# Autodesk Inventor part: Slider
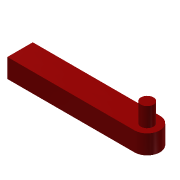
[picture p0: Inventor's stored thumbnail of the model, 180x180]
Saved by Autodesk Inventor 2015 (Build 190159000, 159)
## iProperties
Created: 2019-10
Part Number: Slider
Material: 一般
Document SubType Name: Modeling
Designer: Kuan_Lun Hsu
Density: 1 g/cm^3
Appearance: 紅
Mass: 268.274 g
Surface Area: 342.265 cm^2
Volume: 268.274 cm^3
Author: Kuan_Lun Hsu
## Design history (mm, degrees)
sketch "草圖1" dims "d4" = 60
  geometry: L1 (0, 220)-(200, 220); L2 (200, 220)-(200, 180); L3 (200, 180)-(0, 180); L4 (0, 180)-(0, 220); L5 (-21.213, 21.213)-(21.213, -21.213); L6 (21.213, -21.213)-(289.914, 247.487); L7 (289.914, 247.487)-(247.487, 289.914); L8 (247.487, 289.914)-(-21.213, 21.213); L9 (0, 0)-(200, 200); L10 (141.421, 141.421)-(247.487, 247.487); L11 (134.35, 148.492)-(240.416, 254.558); L12 (254.558, 240.416)-(148.492, 134.35); L13 (236.961, 152.108)-(300, 50); L14 (208.305, 143.231)-(242.687, 32.245); L15 (257.738, 173.749)-(341.553, 93.282); L16 (-60, 180)-(390, 180); L17 (390, 180)-(390, -70); L18 (390, -70)-(-60, -70); L19 (-60, -70)-(-60, 180); C1 r 10 at (200, 200); C2 r 15 at (0, 0); C3 r 30 at (300, 50); A1 r 10 centre (141.421, 141.421) between (134.35, 148.492) and (148.492, 134.35); A2 r 10 centre (247.487, 247.487) between (254.558, 240.416) and (240.416, 254.558); A3 r 60 centre (300, 50) between (242.687, 32.245) and (341.553, 93.282); A4 r 30 centre (236.961, 152.108) between (208.305, 143.231) and (257.738, 173.749); 4 further points
  constraints: 40 end point, 9 parallel, 9 tangent, 8 point on circle, 7 centre point, 4 coincident, 4 midpoint, 3 perpendicular, 2 horizontal, 2 vertical alignment, 1 collinear, 1 equal radius, 1 point on line, 5 other
  dimensions: "d0" = 40 distance between parallel lines of L3 L1; "d1" = 200 distance of L1.start L1.end; "d2" = 180 distance from line of point (0, 0) L3; "d3" = 20 diameter of C1; "d5" = 380 distance of L5.end L6.end; "d6" = 30 distance from line of L7 L10.end; "d7" = 150 distance of L11.start L11.end; "d8" = 60 diameter of A4; "d9" = 120 diameter of A3; "d10" = 120 distance of L13.start L13.end; "d11" = 300 horizontal distance of L13.end point (0, 0); "d12" = 50 vertical distance of point (0, 0) L13.end; "d13" = 60 distance between parallel lines of L19 L4; "d14" = 250 distance of L18.end L16.start; "d15" = 450 distance of L17.end L18.end; "d16" = 45 deg angle of L6 L18 (derived); "d17" = 30 diameter of C2; "d18" = 60 diameter of C3
extrude "擠出1" new body sketch "草圖1" distance "d19" = 30; taper "d20" = 0 deg
extrude "擠出2" join sketch "草圖1" distance "d21" = 30; taper "d22" = 0 deg
node "實體1"
